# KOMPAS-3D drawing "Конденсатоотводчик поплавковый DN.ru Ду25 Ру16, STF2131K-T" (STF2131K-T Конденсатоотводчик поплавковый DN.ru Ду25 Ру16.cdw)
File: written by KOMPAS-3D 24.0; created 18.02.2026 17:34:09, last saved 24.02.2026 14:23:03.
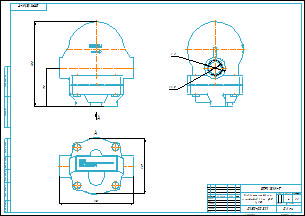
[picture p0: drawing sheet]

Document properties: art: D150-00321; Автор: R2D2; Форматы листов документа: A2; Полное имя файла: STF2131K-T Конденсатоотводчик поплавковый DN.ru Ду25 Ру16 (2d).cdw; Масса: 4; Наименование: Конденсатоотводчик поплавковый DN.ru Ду25 Ру16; Количество листов документа: 1; Примечание: D150-00321

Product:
- Part/product: Конденсатоотводчик поплавковый DN.ru Ду25 Ру16  | designation STF2131K-T
    Масса: 4
    Раздел спецификации: Прочие изделия
    Форматы листов документа: A2
    Примечание: D150-00321
    additional columns: D150-00321

Views: Вид по стрелке А
Referenced files in E:\Работа\Зайцев\Для компаса\: чертеж DN.ru А3.cdt
Referenced files in E:\Работа\Зайцев\STF2131K-T Конденсатоотводчик поплавковый DN.ru Ду15-50 Ру16\DN25\: STF2131K-T Конденсатоотводчик поплавковый DN.ru Ду25 Ру16.m3d
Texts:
  чертеж DN.ru А3.cdt
  Конденсатоотводчик
  поплавковый DN.ru Ду25
  Ру16
  STF2131K-T
  prop
  Конденсатоотводчик поплавковый DN.ru Ду25 Ру16
  STF2131K-T Конденсатоотводчик поплавковый DN.ru Ду25 Ру16
Dimensions and other numbers on the sheet: 1:1; 0; 1; 2; 4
